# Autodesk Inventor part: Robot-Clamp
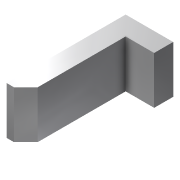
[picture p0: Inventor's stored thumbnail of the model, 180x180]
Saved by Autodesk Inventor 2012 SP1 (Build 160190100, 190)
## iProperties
Shininess: 21.0
Length Units: 11269
Angle Units: 11279
Time Units: 11290
Mass Units: 11283
Length Display Precision: 3
Angle Display Precision: 2
Created: 2001-08
Part Number: Robot-Clamp
Document SubType Name: ﾓﾃﾞﾘﾝｸﾞ
Designer: Administrator
Density: 1 g/cm^3
Material: Default
Density: 0.0
Volumn: 0.0
Area: 0.0
PropertySet Name: Model Information
Control State: 0
Master: False
Checked Out: False
Author: Administrator
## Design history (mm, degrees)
body "Solid1"
sketch "ｽｹｯﾁ1"
  geometry: L1 (-1.849, 20)-(18.151, 20); L2 (18.151, 20)-(18.151, 12); L3 (18.151, 12)-(-1.849, 12); L4 (-1.849, 12)-(-1.849, 20); L5 (-1.849, 20)-(6.151, 20); L6 (6.151, 20)-(6.151, -25); L7 (1.151, -30)-(-1.849, -30); L8 (-1.849, -30)-(-1.849, 20); L9 (6.151, -25)-(1.151, -30); 1 further point
  constraints: 18 end point, 4 parallel, 2 horizontal, 2 perpendicular, 2 point on line
  dimensions: "d0" = 20 distance of L1.start L1.end; "d1" = 8 distance of L1.end L2.end; "d2" = 50 distance of L7.end L1.start; "d3" = 5 distance of L6.end point (6.151, -30); "d4" = 5 distance of L7.start point (6.151, -30) (= d3); "d5" = 8 distance between parallel lines of L8 L6
extrude "Extrusion1" new body sketch "ｽｹｯﾁ1" distance "d6" = 20; taper "d7" = 0 deg
